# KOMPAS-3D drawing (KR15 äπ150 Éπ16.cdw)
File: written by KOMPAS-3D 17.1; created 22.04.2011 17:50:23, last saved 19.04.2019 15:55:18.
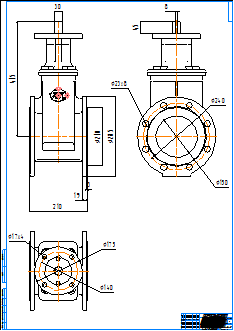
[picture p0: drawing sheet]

Title block, sheet 1: name: KR15 Ду150 Ру16; material: Внимание! Данный продукт является объектом авторского права ООО «Торговый Дом АДЛ». / Запрещается изменение, копирование, распространение / (в том числе путем копирования на другие сайты и ресурсы в Интернете) / или любое иное использование информации и объектов без предварительного / согласия правообладателя (ООО «Торговый Дом АДЛ»).; scale: 1:1; sheets: 1; organisation: ООО "Торговый дом АДЛ"; sheet format: A0; stored path: \\adlc.lan\data\АДЛ_ПКД\3D-модели\ADL production\Клиновые задвижки серии KR ГРАНАР\Клиновые задвижки KR15\С голым штоком\KOMPAS 2D\KR15 Ду150 Ру16.cdw

Views: Спереди 7, Проекционный вид 8, Проекционный вид 9
Dimensions and other numbers on the sheet: 285; 210; 415; 19; 3; 30; 175; 17; 140; 45; 8; 23; 240; 150; 1:1; 1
